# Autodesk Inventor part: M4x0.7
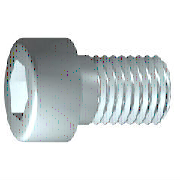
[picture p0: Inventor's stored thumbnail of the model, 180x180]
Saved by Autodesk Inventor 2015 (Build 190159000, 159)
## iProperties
IsCustomPart: 1
Created: 2015-10
Part Number: M4x0.7
Material: 강, 연강
Description: 6각머리 태핑 나사
Document SubType Name: Modeling
Standard: KS B 1003
Designer: mdu
Standards Organization: KS
Language: ko-KR
Size Designation: M 4 x 16
Categories: <MemberInstance><Categories><Category DisplayName="조임쇠" InternalName="e4da775c-781d-43d5-af7c-5136215cf5a6" Mnemonic="FSTN"><Category DisplayName="볼트" InternalN
Density: 1 g/cm^3
Appearance: 강철
Author: mdu
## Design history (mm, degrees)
sketch "스케치1"
  geometry: L1 (-1, 0)-(16, 0); L2 (16, 0)-(16, 2); L3 (16, 2)-(1.75, 2); L4 (1.75, 2)-(1.32, 2); L5 (1.32, 2)-(0, 2); L6 (0, 2)-(0, 3.5); L7 (0, 3.5)-(-4, 3.5); L8 (-4, 3.5)-(-4, 1.732); L9 (-4, 1.732)-(-2, 1.732); L10 (-2, 1.732)-(-1, 0); L11 (-8, 0)-(20, 0) reference; L12 (0, -0.7)-(0, 4.2) reference; L13 (1.75, 2)-(0, 2)
  constraints: 22 end point, 6 parallel, 2 collinear, 2 perpendicular, 1 horizontal, 1 point on line
  dimensions: "d1" = 14.25 distance from line of L3.end L2 (= GEL); "d2" = 0.42952 distance of L4.end L3.end (computed from GAL); "d3" = 4 distance between parallel lines of L8 L6 (= KOH); "d4" = 2 distance of L8.end L9.end (= INTI); "d5" = 60 deg angle of L10 L1; "d6" = 4 diameter of L3 L1 (= GD); "d7" = 4 diameter of L5 L1 (= BDM); "d8" = 3.4641 diameter of L9 L1 (= 1.1547 x SW); "d9" = 7 diameter of L7 L1 (= KOD); "d26" = 16 distance between parallel lines of L12 L2 (= NLG)
revolve "본체" sketch "스케치1" stored, may be unused: angle "d10" = 90 deg
sketch "스케치2"
  geometry: L1 (0, -4.9)-(0, 4.9) reference; L2 (-4.9, 0)-(4.9, 0) reference; L3 (1.732, 0)-(0.866, -1.5); L4 (0.866, -1.5)-(-0.866, -1.5); L5 (-0.866, -1.5)-(-1.732, 0); L6 (-1.732, 0)-(-0.866, 1.5); L7 (-0.866, 1.5)-(0.866, 1.5); L8 (0.866, 1.5)-(1.732, 0); 2 further points
  constraints: 12 end point, 1 coincident, 1 horizontal alignment, 1 point on line, 12 other
extrude "슬롯" join sketch "스케치2" stored distance "d11" = 10; taper "d12" = 0 deg
workplane "Work Plane1"
fillet "Fillet2" dims "d30" = 0.1 (= R)
body "Solid1"
fillet "모깎기1" dims "d17" = 0.4 (= RR)
feature "스레드" dims "d13" = 14.25 (= GEL), "d14" = 0
chamfer "모따기1" distance "d15" = 0.42941 (= -0.5 x SPD + 0.5 x GD); stored, may be unused: second distance "d16" = 0.42941 (= GUL), angle "d27" = 45 deg
other parameters: "GD" = 4 (= NND) [user parameter; used in 2 equation terms], "NLG" = 16 [user parameter; used in 1 equation term], "GEL" = 14.25 [user parameter; used in 2 equation terms], "KOD" = 7 [user parameter; used in 1 equation term], "KOH" = 4 [user parameter; used in 1 equation term], "INTI" = 2 [user parameter; used in 1 equation term], "GAL" = 0.42941 (= 0.61345 x PTC) [user parameter; used in 1 equation term], "GUL" = 0.42941 (= 0.61345 x PTC) [user parameter; used in 1 equation term], "BDM" = 4 (= NND) [user parameter; used in 1 equation term], "SW" = 3 [user parameter; used in 2 equation terms], "RR" = 0.4 [user parameter; used in 1 equation term], "SPD" = 3.14117 (= NND - 1.2269 x PTC) [user parameter; used in 1 equation term], "d19" = 0, "d28" = 0, "d29" = 0, "R" = 0.1 [user parameter; used in 1 equation term], "PHH" = 0.2 [user parameter], "GD1" = 3.14117 (= THREADDIA - 1.2269 x PTC) [user parameter], "THREADDIA" = 4 [user parameter; used in 1 equation term], "FAWI" = 45 deg [user parameter], "TPU" = 14.28571 (computed from PTC) [user parameter], "PTC" = 0.7 [user parameter; used in 5 equation terms], "NND" = 4 [user parameter; used in 3 equation terms], "TOA" = 30 deg [user parameter], "E0" = 3.465 (= 1.155 x SW) [user parameter]
